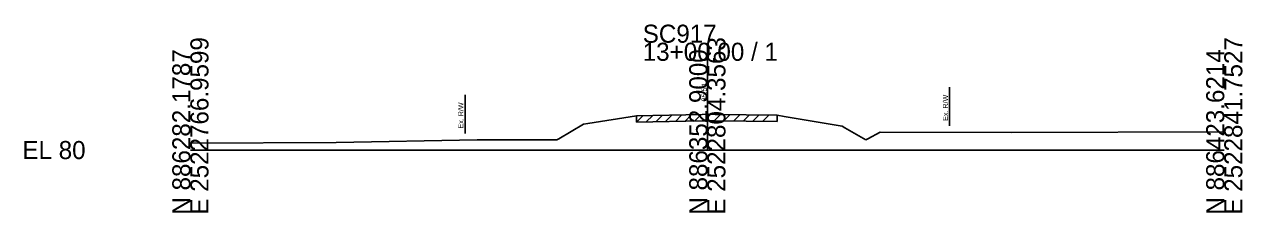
# Model space of a CAD drawing. Extents: x -26 to 218, y -10 to 12021.
# Drawn here: x -25.7 to 162.8, y 10490.3 to 10519.5 of the extents above; entities that cross this region are included whole.
import ezdxf

# ---------------------------------------------------------------- set-up
doc = ezdxf.new("R2010")
doc.units = 0
for name, color, linetype in [('RD_GPK_XS_Cell', 7, 'Continuous'), ('RD_XS_ExGround', 7, 'Continuous'), ('RD_XS_ExPaveRet', 7, 'Continuous'), ('RD_XS_ExRW', 7, 'Continuous'), ('RD_XS_TX_Elev_EX', 7, 'Continuous')]:
    doc.layers.add(name, color=color, linetype=linetype)

msp = doc.modelspace()

# ---------------------------------------------------------------- linework, layer by layer
at = {"layer": 'RD_GPK_XS_Cell'}
for p, q in [((80, 10500), (80, 10516.62)), ((0, 10500), (80, 10500)), ((80, 10500), (160, 10500))]:
    msp.add_line(p, q, dxfattribs=at)
at = {"layer": 'RD_XS_ExGround'}
for p, q in [((61.53, 10504.1), (69.05, 10505.32)), ((69.05, 10505.32), (79.2, 10505.53)), ((79.2, 10505.53), (80.22, 10505.54)), ((80.22, 10505.54), (81.22, 10505.53)), ((81.22, 10505.53), (90.79, 10505.4)), ((90.79, 10505.4), (91.9, 10505.21)), ((91.9, 10505.21), (100.88, 10503.69)), ((57.02, 10501.76), (60.84, 10503.99)), ((60.84, 10503.99), (61.53, 10504.1)), ((100.88, 10503.69), (101.28, 10503.45)), ((101.28, 10503.45), (104.55, 10501.59)), ((22.57, 10501.18), (44.37, 10501.58)), ((44.37, 10501.58), (56.69, 10501.6)), ((56.69, 10501.6), (57.02, 10501.76)), ((104.55, 10501.59), (104.86, 10501.74)), ((104.86, 10501.74), (106.74, 10502.75)), ((106.74, 10502.75), (127.11, 10502.72)), ((127.11, 10502.72), (160, 10502.81)), ((0, 10501.08), (22.57, 10501.18))]:
    msp.add_line(p, q, dxfattribs=at)
at = {"layer": 'RD_XS_ExPaveRet'}
for p, q in [((69.05, 10504.32), (70.07, 10505.34)), ((69.05, 10504.32), (69.05, 10505.32)), ((70.55, 10504.35), (71.57, 10505.37)), ((72.05, 10504.38), (73.07, 10505.4)), ((73.55, 10504.41), (74.57, 10505.43)), ((75.05, 10504.44), (76.07, 10505.46)), ((76.55, 10504.47), (77.57, 10505.49)), ((78.05, 10504.5), (79.07, 10505.52)), ((79.55, 10504.53), (80.55, 10505.54)), ((81.05, 10504.53), (82.03, 10505.52)), ((82.55, 10504.51), (83.53, 10505.49)), ((84.05, 10504.49), (85.03, 10505.47)), ((85.55, 10504.47), (86.53, 10505.45)), ((87.05, 10504.45), (88.03, 10505.43)), ((88.55, 10504.43), (89.53, 10505.41)), ((90.79, 10505.4), (90.79, 10504.4)), ((69.05, 10504.32), (79.2, 10504.53)), ((79.2, 10504.53), (80.22, 10504.54)), ((80.22, 10504.54), (81.22, 10504.53)), ((81.22, 10504.53), (90.79, 10504.4))]:
    msp.add_line(p, q, dxfattribs=at)
at = {"layer": 'RD_XS_ExRW'}
for p, q in [((117.5, 10509.73), (117.5, 10503.73)), ((117.5, 10509.73), (117.5, 10503.73)), ((42.5, 10508.54), (42.5, 10502.54))]:
    msp.add_line(p, q, dxfattribs=at)

# ---------------------------------------------------------------- texts
at = {"layer": 'RD_GPK_XS_Cell'}
for s, p in [('SC917', (70, 10516.62)), ('13+00.00 / 1', (70, 10513.82)), ('EL 80', (-26, 10498.6))]:
    msp.add_text(s, height=2.8, dxfattribs=at).set_placement(p)
for s, p in [('E 2522766.9599', (2.8, 10490)), ('E 2522804.3563', (82.8, 10490)), ('E 2522841.7527', (162.8, 10490)), ('N 886282.1787', (0, 10490)), ('N 886352.9000', (80, 10490)), ('N 886423.6214', (160, 10490))]:
    msp.add_text(s, height=2.8, rotation=90, dxfattribs=at).set_placement(p)
at = {"layer": 'RD_XS_ExRW'}
for p in [(42.25, 10503.33), (117.25, 10504.52), (117.25, 10504.52)]:
    msp.add_text('Ex. R/W ', height=0.8, rotation=90, dxfattribs=at).set_placement(p)
at = {"layer": 'RD_XS_TX_Elev_EX'}
msp.add_text('85.54', height=0.8, rotation=90, dxfattribs=at).set_placement((79.9, 10507.54))

doc.saveas('drawing.dxf')
